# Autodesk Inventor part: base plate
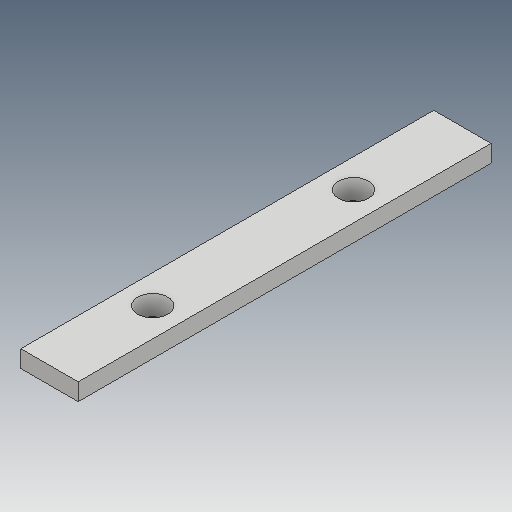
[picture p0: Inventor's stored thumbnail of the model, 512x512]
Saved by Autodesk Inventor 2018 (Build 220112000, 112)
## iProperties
Created: 2016-03
Part Number: base plate
Material: Generic
Document SubType Name: Modeling
Designer: Sandeep
Density: 1 g/cm^3
Appearance: Default
Author: Sandeep
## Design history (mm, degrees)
sketch "Sketch1"
  geometry: L1 (0, 0)-(144, 0); L2 (144, 0)-(144, 20); L3 (144, 20)-(0, 20); L4 (0, 20)-(0, 0)
  constraints: 8 end point, 2 parallel, 1 horizontal, 1 perpendicular
  dimensions: "d0" = 144 distance of L1.start L1.end; "d1" = 20 distance of L1.end L2.end
extrude "Extrusion1" new body sketch "Sketch1" distance "d2" = 6; taper "d3" = 0 deg
sketch "Sketch2"
  geometry: L1 (0, 20)-(0, 0) reference; L2 (0, 10)-(181.292, 10); 2 further points
  constraints: 2 end point, 2 point on line, 1 horizontal, 1 midpoint
  dimensions: "d4" = 70 distance of point (108, 10) point (38, 10); "d5" = 38 distance from line of L1 point (38, 10)
hole "Hole1" sketch "Sketch2" at (38, 10), (108, 10) diameter "d6" = 6; stored, may be unused: countersink angle "d10" = 45 deg, drill point angle "d12" = 118 deg; dims "d7" = 6, "d8" = 10.5, "d9" = 2, "d11" = 8
body "Solid1"
